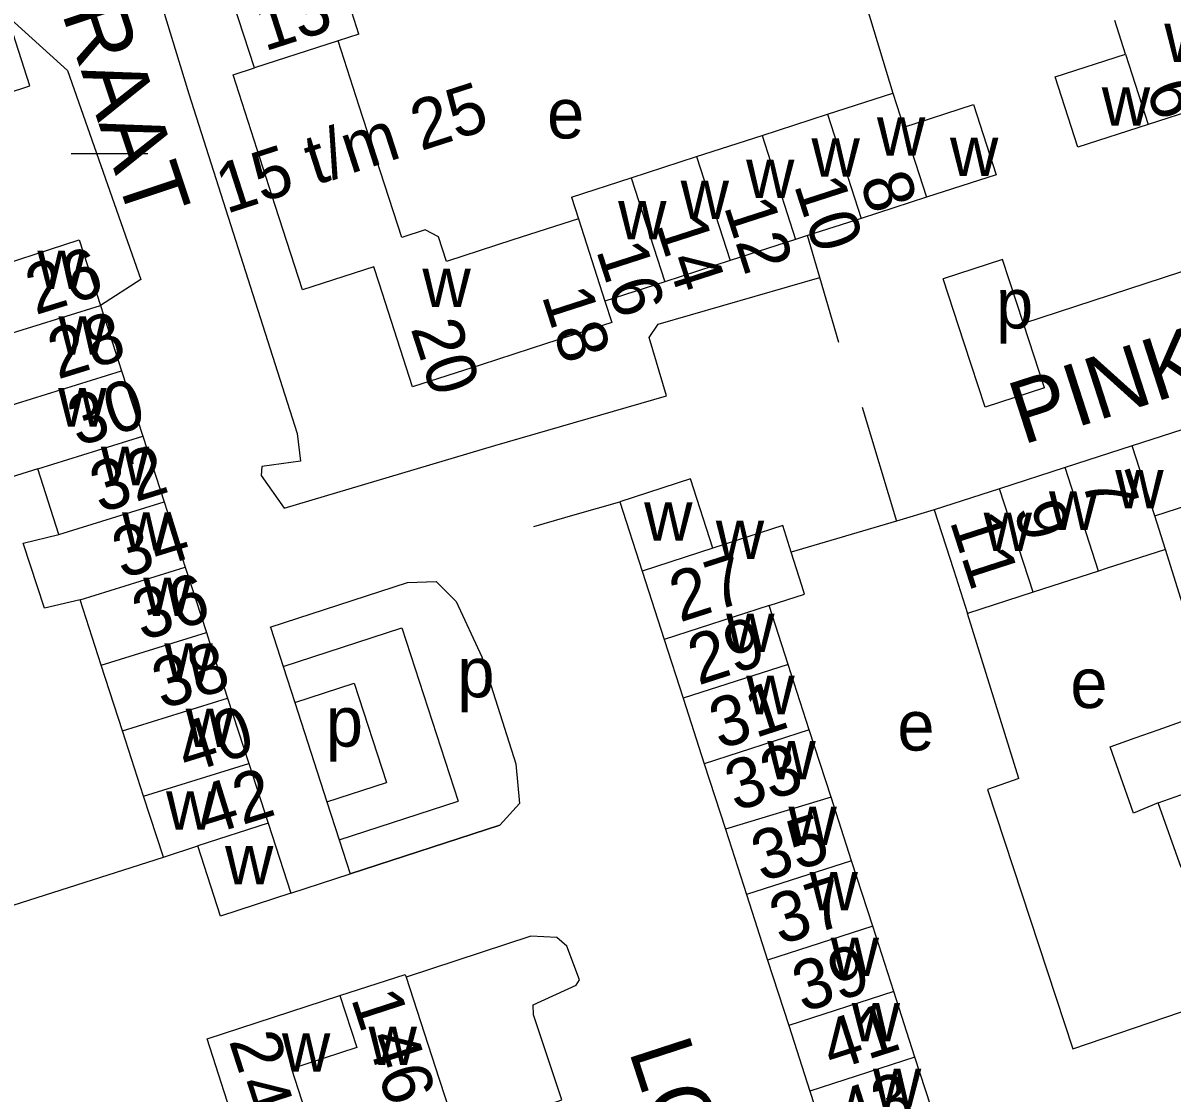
# Model space of a CAD drawing. Extents: x 159261 to 160849, y 382514 to 384534.
# Drawn here: x 159591.4 to 159683.3, y 383141.6 to 383227.2 of the extents above; entities that cross this region are included whole.
import ezdxf

# ---------------------------------------------------------------- set-up
doc = ezdxf.new("R2010")
doc.units = 0
for name, color, linetype in [('BLT_Basislijn', 7, 'Continuous'), ('BLT_Bebouwing', 7, 'Continuous'), ('BLT_Centroide', 7, 'Continuous'), ('BLT_Huisnummer', 7, 'Continuous'), ('BLT_Huisnummer_ tussenligend', 7, 'Continuous'), ('BLT_Huisnummer_reeks', 7, 'Continuous'), ('BLT_Onderverdeling_panden', 7, 'Continuous'), ('BLT_Straatnaam', 7, 'Continuous'), ('BLT_Vlakafsluiter', 7, 'Continuous')]:
    doc.layers.add(name, color=color, linetype=linetype)

msp = doc.modelspace()

# ---------------------------------------------------------------- linework, layer by layer
at = {"layer": 'BLT_Basislijn'}
for p, q in [((159657.26, 383233.951), (159660.993, 383221.599)), ((159655.157, 383206.853), (159654.174, 383210.204)), ((159693.927, 383210.53), (159671.441, 383203.173)), ((159669.763, 383208.301), (159665.011, 383206.746)), ((159671.441, 383203.173), (159669.763, 383208.301)), ((159656.679, 383201.663), (159655.157, 383206.853)), ((159666.689, 383201.618), (159665.011, 383206.746)), ((159673.119, 383198.045), (159671.441, 383203.173)), ((159668.367, 383196.49), (159666.689, 383201.618)), ((159673.119, 383198.045), (159668.367, 383196.49)), ((159658.537, 383196.489), (159661.273, 383187.383)), ((159635.585, 383187.902), (159639.141, 383188.927)), ((159632.264, 383186.945), (159635.585, 383187.902)), ((159664.296, 383188.276), (159661.273, 383187.383)), ((159661.273, 383187.383), (159652.848, 383184.895)), ((159686.783, 383172.308), (159682.805, 383185.112)), ((159671.077, 383166.801), (159666.973, 383179.995)), ((159611.196, 383178.896), (159612.214, 383175.752)), ((159621.723, 383178.846), (159626.209, 383164.993)), ((159612.214, 383175.752), (159613.151, 383172.859)), ((159617.905, 383174.407), (159620.476, 383166.468)), ((159613.151, 383172.859), (159615.721, 383164.921)), ((159615.721, 383164.921), (159616.699, 383161.9)), ((159616.699, 383161.9), (159626.209, 383164.993)), ((159617.587, 383159.16), (159629.557, 383163.053)), ((159616.699, 383161.9), (159617.587, 383159.16)), ((159584.544, 383154.711), (159602.64, 383160.51)), ((159612.832, 383157.613), (159617.587, 383159.16))]:
    msp.add_line(p, q, dxfattribs=at)
for points in [[(159590.812, 383266.87), (159591.598, 383264.267), (159604.671, 383221.537), (159613.332, 383194.371), (159613.599, 383192.174), (159610.511, 383191.748), (159610.466, 383191.028), (159612.313, 383188.417), (159629.163, 383193.416)], [(159629.163, 383193.416), (159642.88, 383197.396), (159641.51, 383202.064), (159642.211, 383203.127), (159655.157, 383206.853)], [(159611.194, 383178.903), (159622.17, 383182.475), (159624.463, 383182.539), (159626.067, 383180.96), (159628.118, 383176.527), (159630.831, 383167.956), (159631.117, 383164.804), (159629.557, 383163.053)], [(159612.214, 383175.752), (159621.723, 383178.846)], [(159613.151, 383172.859), (159617.905, 383174.407)], [(159615.721, 383164.921), (159620.476, 383166.468)], [(159671.077, 383166.801), (159668.562, 383165.925), (159675.386, 383145.165), (159687.69, 383149.36)], [(159629.557, 383163.053), (159617.587, 383159.16)], [(159631.823, 383140.148), (159634.506, 383141.103), (159632.251, 383147.885), (159632.226, 383148.7), (159635.665, 383150.279), (159635.932, 383150.706), (159634.919, 383153.393), (159634.123, 383154.093), (159632.022, 383154.176), (159622.061, 383150.907)]]:
    msp.add_lwpolyline(points, dxfattribs=at)
at = {"layer": 'BLT_Bebouwing'}
for p, q in [((159618.283, 383226.323), (159616.588, 383231.556)), ((159609.918, 383223.62), (159608.227, 383228.854)), ((159679.596, 383224.722), (159678.732, 383227.401)), ((159618.283, 383226.323), (159616.618, 383225.785)), ((159618.309, 383220.552), (159616.618, 383225.785)), ((159655.761, 383219.908), (159660.993, 383221.599)), ((159660.993, 383221.599), (159661.872, 383218.878)), ((159686.662, 383220.774), (159681.417, 383219.082)), ((159621.701, 383210.056), (159618.309, 383220.552)), ((159650.527, 383218.217), (159655.761, 383219.908)), ((159645.293, 383216.526), (159650.527, 383218.217)), ((159640.06, 383214.835), (159645.293, 383216.526)), ((159635.274, 383213.289), (159640.06, 383214.835)), ((159613.774, 383205.858), (159611.594, 383212.603)), ((159635.274, 383213.289), (159635.836, 383211.55)), ((159663.681, 383213.276), (159658.448, 383211.585)), ((159635.836, 383211.55), (159630.603, 383209.859)), ((159658.448, 383211.585), (159654.174, 383210.204)), ((159630.603, 383209.859), (159625.293, 383208.143)), ((159653.215, 383209.894), (159647.981, 383208.203)), ((159654.174, 383210.204), (159653.215, 383209.894)), ((159647.981, 383208.203), (159642.747, 383206.511)), ((159642.747, 383206.511), (159637.962, 383204.965)), ((159597.609, 383204.623), (159599.303, 383199.39)), ((159633.281, 383201.567), (159628.047, 383199.875)), ((159599.303, 383199.39), (159600.997, 383194.158)), ((159600.997, 383194.158), (159602.692, 383188.924)), ((159680.129, 383193.393), (159674.763, 383191.659)), ((159594.283, 383186.317), (159592.588, 383191.551)), ((159674.763, 383191.659), (159669.53, 383189.968)), ((159669.53, 383189.968), (159664.296, 383188.276)), ((159602.692, 383188.924), (159604.387, 383183.692)), ((159639.141, 383188.927), (159640.934, 383183.371)), ((159682.805, 383185.112), (159681.935, 383187.805)), ((159604.387, 383183.692), (159606.081, 383178.459)), ((159640.934, 383183.371), (159642.697, 383177.91)), ((159677.439, 383183.378), (159672.206, 383181.687)), ((159672.206, 383181.687), (159666.973, 383179.995)), ((159597.672, 383175.852), (159595.977, 383181.085)), ((159652.617, 383175.922), (159651.1, 383180.623)), ((159606.081, 383178.459), (159606.439, 383177.356)), ((159642.697, 383177.91), (159644.215, 383173.209)), ((159599.367, 383170.618), (159597.672, 383175.852)), ((159654.307, 383170.688), (159652.617, 383175.922)), ((159644.215, 383173.209), (159645.904, 383167.975)), ((159601.061, 383165.386), (159599.367, 383170.618)), ((159645.904, 383167.975), (159647.593, 383162.741)), ((159602.64, 383160.51), (159601.061, 383165.386)), ((159684.04, 383159.666), (159682.204, 383164.851)), ((159611.016, 383163.221), (159605.399, 383161.403)), ((159647.593, 383162.741), (159649.283, 383157.507)), ((159602.64, 383160.51), (159605.399, 383161.403)), ((159659.375, 383154.985), (159657.686, 383160.219)), ((159649.283, 383157.507), (159650.972, 383152.273)), ((159661.065, 383149.751), (159659.375, 383154.985)), ((159650.972, 383152.273), (159652.662, 383147.039)), ((159622.061, 383150.907), (159624.683, 383142.835)), ((159662.754, 383144.517), (159661.065, 383149.751)), ((159652.662, 383147.039), (159654.351, 383141.804)), ((159624.683, 383142.835), (159625.718, 383139.649)), ((159654.351, 383141.804), (159656.041, 383136.57))]:
    msp.add_line(p, q, dxfattribs=at)
for points in [[(159586.261, 383220.303), (159591.966, 383222.185), (159590.164, 383227.752)], [(159681.417, 383219.082), (159675.798, 383217.268), (159673.978, 383222.908), (159679.596, 383224.722)], [(159611.594, 383212.603), (159608.212, 383223.069), (159609.918, 383223.62)], [(159661.872, 383218.878), (159667.434, 383220.676), (159669.244, 383215.074), (159663.681, 383213.276)], [(159625.293, 383208.143), (159624.657, 383210.109), (159623.576, 383210.662), (159621.701, 383210.056)], [(159587.539, 383207.143), (159595.914, 383209.856), (159597.609, 383204.623)], [(159619.89, 383206.397), (159619.469, 383207.7), (159613.774, 383205.858)], [(159628.047, 383199.875), (159622.57, 383198.105), (159619.89, 383206.397)], [(159637.962, 383204.965), (159638.514, 383203.258), (159633.281, 383201.567)], [(159592.588, 383191.551), (159589.087, 383190.466), (159587.459, 383195.718), (159590.894, 383196.783)], [(159681.935, 383187.805), (159687.477, 383189.597), (159685.671, 383195.184), (159680.129, 383193.393)], [(159646.603, 383185.201), (159644.809, 383190.757), (159639.141, 383188.927)], [(159664.296, 383188.276), (159665.834, 383183.519), (159666.973, 383179.995)], [(159652.848, 383184.895), (159652.176, 383187.036), (159646.603, 383185.201)], [(159595.977, 383181.085), (159593.118, 383180.411), (159591.435, 383185.624), (159594.283, 383186.317)], [(159646.603, 383185.201), (159640.934, 383183.371)], [(159651.1, 383180.623), (159653.932, 383181.537), (159653.705, 383182.24), (159652.848, 383184.895)], [(159682.805, 383185.112), (159678.048, 383183.575), (159677.439, 383183.378)], [(159606.439, 383177.356), (159607.776, 383173.225)], [(159607.776, 383173.225), (159609.471, 383167.993)], [(159680.368, 383170.037), (159682.204, 383170.687), (159686.783, 383172.308)], [(159656.047, 383165.297), (159654.307, 383170.688)], [(159682.204, 383164.851), (159680.246, 383164.019), (159678.366, 383169.328), (159680.368, 383170.037)], [(159609.471, 383167.993), (159611.016, 383163.221)], [(159657.686, 383160.219), (159656.047, 383165.297)], [(159611.016, 383163.221), (159612.832, 383157.613)], [(159612.832, 383157.613), (159607.215, 383155.794), (159605.399, 383161.403)], [(159616.759, 383149.43), (159621.989, 383151.129), (159622.061, 383150.907)], [(159607.995, 383140.252), (159606.135, 383145.979), (159616.759, 383149.43)], [(159662.767, 383138.741), (159664.444, 383139.282), (159662.754, 383144.517)]]:
    msp.add_lwpolyline(points, dxfattribs=at)
at = {"layer": 'BLT_Onderverdeling_panden'}
for p, q in [((159616.618, 383225.785), (159609.918, 383223.62)), ((159679.596, 383224.722), (159681.417, 383219.082)), ((159655.761, 383219.908), (159658.448, 383211.585)), ((159661.872, 383218.878), (159663.681, 383213.276)), ((159650.527, 383218.217), (159653.215, 383209.894)), ((159645.293, 383216.526), (159647.981, 383208.203)), ((159640.06, 383214.835), (159642.747, 383206.511)), ((159635.836, 383211.55), (159637.962, 383204.965)), ((159589.199, 383202.016), (159597.609, 383204.623)), ((159590.894, 383196.783), (159599.303, 383199.39)), ((159592.588, 383191.551), (159600.997, 383194.158)), ((159681.935, 383187.805), (159680.129, 383193.393)), ((159677.439, 383183.378), (159674.763, 383191.659)), ((159672.206, 383181.687), (159669.53, 383189.968)), ((159594.283, 383186.317), (159602.692, 383188.924)), ((159595.977, 383181.085), (159604.387, 383183.692)), ((159651.1, 383180.623), (159642.697, 383177.91)), ((159597.672, 383175.852), (159606.081, 383178.459)), ((159652.617, 383175.922), (159644.215, 383173.209)), ((159599.367, 383170.618), (159607.776, 383173.225)), ((159654.307, 383170.688), (159645.904, 383167.975)), ((159601.061, 383165.386), (159609.471, 383167.993)), ((159682.204, 383164.851), (159690.412, 383167.759)), ((159656.047, 383165.297), (159647.593, 383162.741)), ((159657.686, 383160.219), (159649.283, 383157.507)), ((159659.375, 383154.985), (159650.972, 383152.273)), ((159661.065, 383149.751), (159652.662, 383147.039)), ((159662.754, 383144.517), (159654.351, 383141.804))]:
    msp.add_line(p, q, dxfattribs=at)
msp.add_lwpolyline([(159616.759, 383149.43), (159618.106, 383145.284), (159612.875, 383143.584), (159614.222, 383139.438)], dxfattribs=at)
at = {"layer": 'BLT_Vlakafsluiter'}
msp.add_line((159595.273, 383216.773), (159601.391, 383216.773), dxfattribs=at)
msp.add_lwpolyline([(159590.164, 383227.752), (159594.966, 383223.42), (159600.823, 383206.686), (159597.609, 383204.623)], dxfattribs=at)

# ---------------------------------------------------------------- texts
at = {"layer": 'BLT_Centroide'}
for s, p in [('w', (159682.703, 383224.094)), ('w', (159677.703, 383218.984)), ('e', (159633.332, 383217.974)), ('w', (159659.719, 383216.594)), ('w', (159654.484, 383214.906)), ('w', (159665.562, 383214.969)), ('w', (159649.25, 383213.219)), ('w', (159644.016, 383211.531)), ('w', (159639.016, 383209.906)), ('w', (159592.562, 383205.938)), ('w', (159623.359, 383204.484)), ('p', (159669.243, 383202.779)), ('w', (159594.25, 383200.688)), ('w', (159594.227, 383194.938)), ('w', (159597.641, 383190.25)), ('w', (159678.781, 383188.391)), ('w', (159673.484, 383186.672)), ('w', (159641.097, 383185.799)), ('w', (159599.336, 383185)), ('w', (159668.25, 383184.984)), ('w', (159646.828, 383184.344)), ('w', (159601.031, 383179.781)), ('w', (159647.656, 383176.906)), ('w', (159602.719, 383174.531)), ('p', (159626.152, 383173.287)), ('w', (159649.266, 383171.938)), ('e', (159675.188, 383172.431)), ('w', (159604.422, 383169.312)), ('p', (159615.635, 383169.343)), ('e', (159661.349, 383169.03)), ('w', (159650.953, 383166.719)), ('w', (159602.857, 383162.69)), ('w', (159652.641, 383161.469)), ('w', (159607.573, 383158.326)), ('w', (159654.328, 383156.25)), ('w', (159656.016, 383151)), ('w', (159657.703, 383145.781)), ('w', (159612.125, 383143.344)), ('w', (159619.055, 383143.875)), ('w', (159659.398, 383140.531))]:
    msp.add_text(s, height=4, dxfattribs=at).set_placement(p)
at = {"layer": 'BLT_Huisnummer'}
for s, rotation, p in [('6', 287.88463, (159681.227, 383222.036)), ('8', 287.89418, (159658.323, 383214.58)), ('12', 287.90022, (159647.445, 383212.556)), ('26', 17.22281, (159592.401, 383203.835)), ('16', 287.89848, (159637.229, 383209.038)), ('30', 17.22474, (159595.778, 383193.327)), ('7', 287.90821, (159676.05, 383190.614)), ('34', 17.22281, (159599.346, 383182.754)), ('11', 287.91147, (159665.517, 383187.386)), ('27', 17.89324, (159643.951, 383179.261)), ('38', 17.22474, (159602.535, 383172.314)), ('31', 17.88706, (159647.141, 383169.1)), ('42', 17.2226, (159606.103, 383162.18)), ('35', 17.88706, (159650.507, 383158.502)), ('39', 17.89324, (159653.789, 383148.061)), ('43', 17.89144, (159657.265, 383137.838))]:
    msp.add_text(s, height=4, rotation=rotation, dxfattribs=at).set_placement(p)
at = {"layer": 'BLT_Huisnummer_ tussenligend'}
for s, rotation, p in [('13', 17.90731, (159610.734, 383224.917)), ('10', 287.89418, (159653.055, 383214.259)), ('14', 287.90022, (159641.987, 383211.104)), ('28', 17.22281, (159594.183, 383198.688)), ('32', 17.22474, (159597.564, 383188.003)), ('9', 287.90821, (159670.601, 383188.298)), ('36', 17.22281, (159600.945, 383177.782)), ('29', 17.89324, (159645.426, 383174.227)), ('40', 17.22474, (159604.48, 383167.162)), ('33', 17.88706, (159648.391, 383164.134)), ('37', 17.88706, (159651.961, 383153.462)), ('41', 17.89324, (159656.111, 383143.376))]:
    msp.add_text(s, height=4, rotation=rotation, dxfattribs=at).set_placement(p)
at = {"layer": 'BLT_Huisnummer_reeks'}
for s, rotation, p in [('15 t/m 25', 17.90838, (159607.672, 383211.925)), ('18', 287.89293, (159632.881, 383205.411)), ('20', 287.91099, (159622.399, 383202.796)), ('1', 287.99854, (159617.624, 383149.219)), ('2', 287.99263, (159607.859, 383145.825)), ('46', 287.99517, (159618.856, 383146.068)), ('44', 287.99854, (159608.407, 383142.378))]:
    msp.add_text(s, height=4, rotation=rotation, dxfattribs=at).set_placement(p)
at = {"layer": 'BLT_Straatnaam'}
for s, rotation, p in [('LOGGERSTRAAT', 288.43189, (159582.745, 383263.241)), ('PINKSTRAAT', 17.90986, (159671.375, 383193.461)), ('LOGGERSTRAAT', 287.9937, (159639.85, 383145.018))]:
    msp.add_text(s, height=5, rotation=rotation, dxfattribs=at).set_placement(p)

doc.saveas('drawing.dxf')
